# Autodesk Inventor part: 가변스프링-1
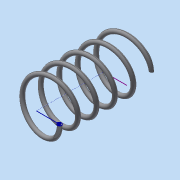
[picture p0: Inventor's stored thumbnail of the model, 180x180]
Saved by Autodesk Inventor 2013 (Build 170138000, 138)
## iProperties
Created: 2020-07
Part Number: 가변스프링-1
Material: 스테인리스강
Document SubType Name: Modeling
Designer: dgall
Density: 8.08 g/cm^3
Mass: 8.70386 g
Surface Area: 21.6894 cm^2
Volume: 1.07721 cm^3
Author: dgall
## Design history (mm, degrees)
sketch "스케치1"
  geometry: L1 (11, 0)-(0, 0); L2 (0, 0)-(0, 32.11); L3 (0, 32.11)-(11, 32.11); C1 r 1 at (11, 0)
  constraints: 6 end point, 2 horizontal, 1 centre point, 1 coincident, 1 perpendicular, 1 vertical alignment
  dimensions: "d0" = 2 diameter of C1; "d2" = 32.11 dimension on L1.end L2.end (derived); "d3" = 11 distance of L2.end L3.end
feature "코일1" pitch "d4" = 10; turns "d6" = 5; dims "d5" = 32.11 (= d2), "d7" = 0, angle "d8" = 90 deg, angle "d9" = 90 deg, "d10" = 0, "d11" = 0
node "작업 평면2"
  node "작업 평면1"
feature "분할1"
feature "분할2"
node "솔리드1"
other parameters: "d12" = 0, "d13" = 0
